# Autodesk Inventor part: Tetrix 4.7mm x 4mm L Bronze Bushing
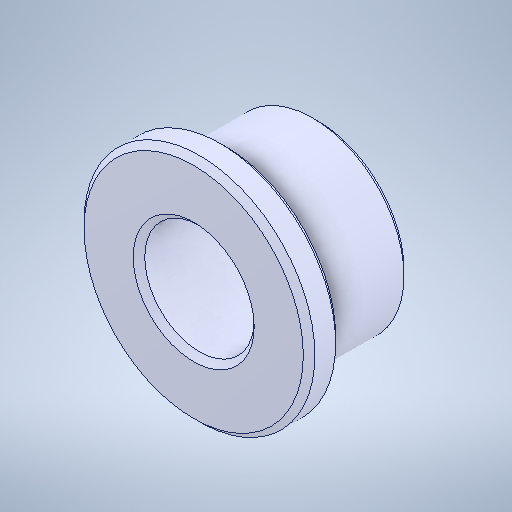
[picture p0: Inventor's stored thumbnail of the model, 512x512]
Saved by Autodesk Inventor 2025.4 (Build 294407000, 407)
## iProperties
Created: 2021-10
Part Number: Tetrix 4.7mm x 4mm L Bronze Bushing
Material: Genérico
Document SubType Name: Modeling
Designer: usuario
Density: 1 g/cm^3
Appearance: Valor por defecto
Author: usuario
Sending System: SolidWorks 2016
Last Author: LENOVO
Last Saved: 2021-10-26
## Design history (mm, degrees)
feature "Revolve1"
node "Sólido1"
